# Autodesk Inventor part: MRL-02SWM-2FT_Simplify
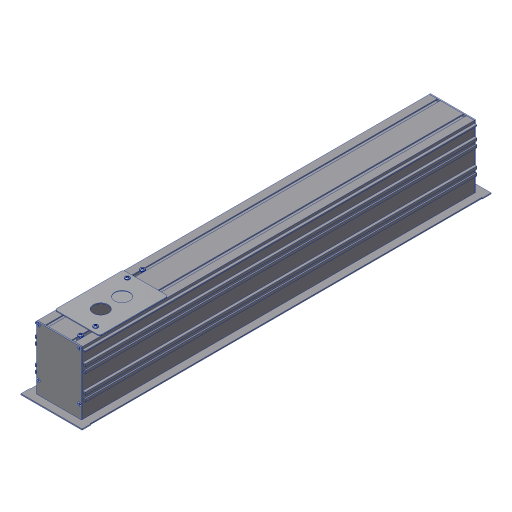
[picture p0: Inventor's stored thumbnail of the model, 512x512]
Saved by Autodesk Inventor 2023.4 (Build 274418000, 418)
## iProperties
description: 0:0:2.5" Recessed Static White Slot Light
manufacturer: 0:0:The Kirlin Company
model: 0:0:MRL-02SWM-2FT
url: 0:0:
load_classification: Lighting
motor: 0 ul
Part Number: MRL-02SWM-2FT_Simplify
Material: Generic
Document SubType Name: Modeling
Designer: sjaafar
Manufacturer: Standard
Standards Organization: Custom
Mass: 542.399 g
Surface Area: 6502.82 cm^2
Volume: 542.399 cm^3
Density: 1 g/cm^3
Appearance: Aluminum - Flat
Author: sjaafar
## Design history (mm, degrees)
derived "MRL-02SWM-2FT.iam"
body "Solid9"
node "845032-02288-XX.ipt:1"
node "845035-00-00.ipt:1"
node "845035-00-00.ipt:2"
node "725760-02288:1"
node "725610-02288:1"
node "509300-00-00:1"
node "850013-01-00.iam:1::520102-00-00.ipt:1"
node "850013-01-00.iam:1::503029-00-00.ipt:1"
node "850013-01-00.iam:2::520102-00-00.ipt:1"
node "850013-01-00.iam:2::503029-00-00.ipt:1"
node "503029-00-00.ipt:1"
node "503029-00-00.ipt:2"
node "503018-00-00.ipt:1"
node "503018-00-00.ipt:2"
node "503018-00-00.ipt:3"
node "503018-00-00.ipt:4"
node "503018-00-00.ipt:5"
node "503018-00-00.ipt:6"
node "503018-00-00.ipt:7"
node "503018-00-00.ipt:8"
node "509064-00-00.ipt:5"
node "509053-00-00 COILED.ipt:1"
node "501018-00-00.ipt:1"
other parameters: "d15" = 61.595, "d16" = 9.525, "d17" = 9.525, "d35" = 5.08
